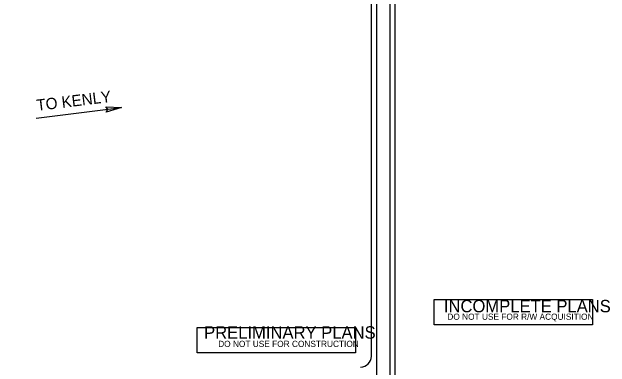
# Model space of a CAD drawing. Extents: x 2241278 to 2254132, y 649924 to 670434.
# Drawn here: x 2251201 to 2253976, y 661974 to 663621 of the extents above; entities that cross this region are included whole.
import ezdxf

# ---------------------------------------------------------------- set-up
doc = ezdxf.new("R2010")
doc.units = 0
for name, color, linetype in [('Prop RDY Alternate Text Yellow', 7, 'Continuous'), ('Prop Terminator CELL', 7, 'Continuous'), ('Sheet Plot Border Inside CELL', 7, 'Continuous'), ('Sheet Plot Border Outside CELL', 7, 'Continuous'), ('Sheet Sticker Incomplete CELL', 7, 'Continuous'), ('Sheet Sticker Preliminary CELL', 7, 'Continuous'), ('Sheet Title CELL', 7, 'Continuous')]:
    doc.layers.add(name, color=color, linetype=linetype)

msp = doc.modelspace()

# ---------------------------------------------------------------- linework, layer by layer
at = {"layer": 'Prop RDY Alternate Text Yellow'}
msp.add_line((2251313.7, 663128.3), (2251708.8, 663178.5), dxfattribs=at)
at = {"layer": 'Prop Terminator CELL'}
msp.add_lwpolyline([(2251635.8, 663181.8), (2251708.8, 663178.5), (2251638.6, 663156.7), (2251646.1, 663170.6)], close=True, dxfattribs=at)
at = {"layer": 'Sheet Plot Border Inside CELL'}
msp.add_lwpolyline([(2244623.8, 661011.4), (2252956.3, 661011.4), (2252956.3, 666286.9), (2244623.8, 666286.9)], close=True, dxfattribs=at)
at = {"layer": 'Sheet Plot Border Outside CELL'}
msp.add_lwpolyline([(2252978.8, 666399.1), (2244558.8, 666399.1), (2244558.8, 660899.2), (2252978.8, 660899.2)], close=True, dxfattribs=at)
at = {"layer": 'Sheet Sticker Incomplete CELL'}
msp.add_lwpolyline([(2253160.5, 662169.6), (2253160.5, 662287.1), (2253895.5, 662287.1), (2253895.5, 662169.6)], close=True, dxfattribs=at)
at = {"layer": 'Sheet Sticker Preliminary CELL'}
msp.add_lwpolyline([(2252059.9, 662040.1), (2252059.9, 662157.6), (2252794.9, 662157.6), (2252794.9, 662040.1)], close=True, dxfattribs=at)
at = {"layer": 'Sheet Title CELL'}
for points in [[(2252868.8, 662024.1), (2252868.8, 666199.2)], [(2252893.8, 661074.2), (2252893.8, 666224.1)]]:
    msp.add_lwpolyline(points, dxfattribs=at)
msp.add_arc((2252818.8, 662024.4), 50, 270, 360, dxfattribs=at)

# ---------------------------------------------------------------- texts
at = {"layer": 'Prop RDY Alternate Text Yellow'}
msp.add_text('TO KENLY', height=52.59, rotation=6.9264, dxfattribs=at).set_placement((2251317.9, 663162))
at = {"layer": 'Sheet Sticker Incomplete CELL'}
for s, height, p in [('INCOMPLETE PLANS', 57.6, (2253205.3, 662228.1)), ('DO NOT USE FOR R/W ACQUISITION', 28.8, (2253221.5, 662193.4))]:
    msp.add_text(s, height=height, dxfattribs=at).set_placement(p)
at = {"layer": 'Sheet Sticker Preliminary CELL'}
for s, height, p in [('PRELIMINARY PLANS', 57.6, (2252092.4, 662105.8)), ('DO NOT USE FOR CONSTRUCTION', 28.8, (2252157.9, 662067.3))]:
    msp.add_text(s, height=height, dxfattribs=at).set_placement(p)

doc.saveas('drawing.dxf')
